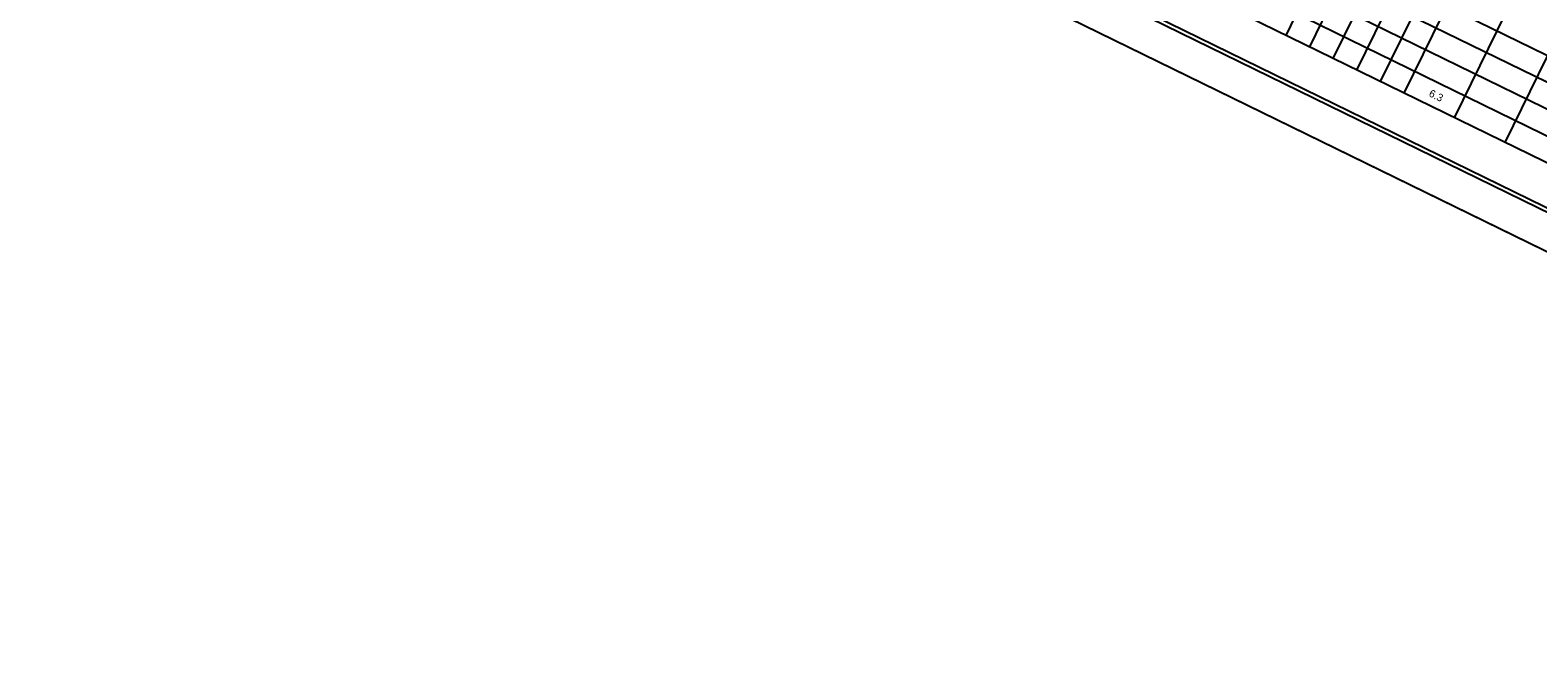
# Model space of a CAD drawing. Extents: x 1523741 to 1527628, y 632733 to 635404.
# Drawn here: x 1523818 to 1524772, y 633628 to 634021 of the extents above; entities that cross this region are included whole.
import ezdxf

# ---------------------------------------------------------------- set-up
doc = ezdxf.new("R2010")
doc.units = 0
for name, color, linetype in [('Sheet Cutting Line CELL', 7, 'Continuous'), ('Sheet Plot Border Inside CELL', 7, 'Continuous'), ('Sheet Plot Border Outside CELL', 7, 'Continuous'), ('Sheet Summary Combination CELL', 7, 'Continuous'), ('Sheet Summary Combination Grid CELL', 7, 'Continuous')]:
    doc.layers.add(name, color=color, linetype=linetype)

msp = doc.modelspace()

# ---------------------------------------------------------------- linework, layer by layer
at = {"layer": 'Sheet Cutting Line CELL'}
msp.add_line((1523817.5, 634350.36), (1525330.27, 633610.5), dxfattribs=at)
at = {"layer": 'Sheet Plot Border Inside CELL'}
msp.add_lwpolyline([(1525799.64, 634580.45), (1524302.6, 635312.63), (1523839.04, 634364.81), (1525336.09, 633632.64)], close=True, dxfattribs=at)
at = {"layer": 'Sheet Plot Border Outside CELL'}
msp.add_lwpolyline([(1525813.55, 634598.64), (1524300.78, 635338.51), (1523817.5, 634350.36), (1525330.27, 633610.5)], close=True, dxfattribs=at)
at = {"layer": 'Sheet Summary Combination CELL'}
msp.add_lwpolyline([(1525787.29, 634583.66), (1524439.82, 635242.68), (1523978.5, 634299.44), (1525325.98, 633640.42)], close=True, dxfattribs=at)
at = {"layer": 'Sheet Summary Combination Grid CELL'}
for p, q in [((1525363.92, 633718.01), (1524016.45, 634377.03)), ((1525357.22, 633704.31), (1524009.75, 634363.33)), ((1525350.52, 633690.61), (1524003.05, 634349.63)), ((1525343.8, 633676.87), (1523996.33, 634335.89)), ((1525343.8, 633676.87), (1523996.33, 634335.89)), ((1525337.1, 633663.17), (1523989.63, 634322.19)), ((1524687.05, 633981.09), (1524804.18, 634220.64)), ((1524750.89, 633949.87), (1524868.09, 634189.49)), ((1524642.16, 634003.05), (1524711.94, 634145.75)), ((1524718.96, 633965.49), (1524803.62, 634138.59)), ((1524612.25, 634017.68), (1524658.81, 634112.9)), ((1524627.21, 634010.36), (1524673.77, 634105.59)), ((1524657.12, 633995.73), (1524703.68, 634090.96)), ((1524672.12, 633988.39), (1524718.68, 634083.62))]:
    msp.add_line(p, q, dxfattribs=at)

# ---------------------------------------------------------------- texts
at = {"layer": 'Sheet Summary Combination CELL'}
msp.add_text('6.3', height=4.8, rotation=333.93772, dxfattribs=at).set_placement((1524702.18, 633979.36))

doc.saveas('drawing.dxf')
